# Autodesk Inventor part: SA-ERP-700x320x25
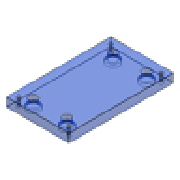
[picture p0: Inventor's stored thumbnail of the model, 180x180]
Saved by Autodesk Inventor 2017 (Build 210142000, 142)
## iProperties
Created: 2016-02
Part Number: SA-ERP-700x320x25
Material: S 55 C
Description: Ejector Retainer Plate
Document SubType Name: Modeling
Designer: Sandeep
Standard Revision: 1
Manufacturer: FUTABA
Language: en-US
Size Designation: 700x320x25
Categories: <MemberInstance><Categories><Category DisplayName="Mold" InternalName="349578f2-f4d4-4954-8c09-8e99297a61c0" Mnemonic="MOLD"><Category DisplayName="Mold Plates"
Density: 7.85 g/cm^3
Appearance: Clear - Blue
IsCustomPart: 1
Author: Sandeep
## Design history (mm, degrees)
sketch "Sketch1"
  geometry: L1 (-160, 350)-(160, 350); L2 (160, 350)-(160, -350); L3 (160, -350)-(-160, -350); L4 (-160, -350)-(-160, 350); 5 further points
  constraints: 8 end point, 2 midpoint, 2 parallel, 1 horizontal, 1 horizontal alignment, 1 perpendicular, 1 vertical alignment
  dimensions: "d84" = 320 distance between parallel lines of L2 L4 (= W_); "d85" = 700 distance between parallel lines of L3 L1 (= L); "d86" = 147 horizontal distance of point (0, 0) point (-147, 337) (= 0.5 x S2_W); "d87" = 337 vertical distance of point (0, 0) point (-147, 337) (= 0.5 x S2_L); "d88" = 128 horizontal distance of point (0, 0) point (-128, 317) (= 0.5 x RP_W); "d89" = 317 vertical distance of point (0, 0) point (-128, 317) (= 0.5 x RP_L)
extrude "Extrusion1" new body sketch "Sketch1" distance "d20" = 25 (= H_); taper "d30" = 0 deg
body "Solid1"
hole "Hole1" sketch "Sketch1" diameter "d90" = 10.106; stored, may be unused: countersink angle "d94" = 90 deg, drill point angle "d96" = 0 deg; dims "d91" = 6, "d92" = 4, "d93" = 2, "d95" = 25 (= H_)
pattern_linear "Rectangular Pattern1" dims "d99" = 674 (computed from S2_L, Nl), "d102" = 294 (computed from S2_W, Nw)
hole "Hole2" sketch "Sketch1" diameter "d103" = 30 (= RP_d1); stored, may be unused: countersink angle "d107" = 90 deg, drill point angle "d109" = 0 deg; dims "d104" = 6, "d105" = 36 (= RP_d2), "d106" = 4 (= RP_k), "d108" = 25 (= H_)
pattern_linear "Rectangular Pattern2" dims "d112" = 634 (computed from RP_L, Nl), "d115" = 256 (computed from RP_W, Nw)
chamfer "Chamfer1" distance "d116" = 0.5; stored, may be unused: second distance "d117" = 2, angle "d118" = 45 deg
other parameters: "L" = 700 [user parameter; used in 1 equation term], "W_" = 320 [user parameter; used in 1 equation term], "H_" = 25 [user parameter; used in 3 equation terms], "S2_W" = 294 [user parameter; used in 2 equation terms], "S2_L" = 674 [user parameter; used in 2 equation terms], "RP_k" = 4 [user parameter; used in 1 equation term], "RP_d1" = 30 [user parameter; used in 1 equation term], "RP_d2" = 36 [user parameter; used in 1 equation term], "RP_L" = 634 [user parameter; used in 2 equation terms], "RP_W" = 256 [user parameter; used in 2 equation terms]
